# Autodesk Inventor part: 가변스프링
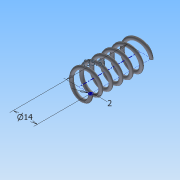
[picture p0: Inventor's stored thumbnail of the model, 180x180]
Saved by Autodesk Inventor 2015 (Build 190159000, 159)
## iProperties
Created: 2020-02
Part Number: 가변스프링
Material: 일반
Document SubType Name: Modeling
Designer: user
Density: 1 g/cm^3
Appearance: 기본값
Mass: 0.819106 g
Surface Area: 16.6202 cm^2
Volume: 0.819106 cm^3
Author: user
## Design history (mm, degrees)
sketch "스케치1"
  geometry: L1 (0, 0)-(7, 0); L2 (7, 0)-(7, 35.5); L3 (7, 35.5)-(0, 35.5); L4 (0, 35.5)-(0, 0); C1 r 1 at (7, 0)
  constraints: 8 end point, 2 parallel, 1 centre point, 1 coincident, 1 horizontal, 1 perpendicular
  dimensions: "d0" = 35.5 distance of L3.end L1.start (derived); "d1" = 2 diameter of C1; "d2" = 14 diameter of L2 L4
feature "코일1" sketch "스케치1" pitch "d3" = 10; turns "d5" = 6; dims "d4" = 35.5 (= d0), "d6" = 0, angle "d7" = 90 deg, angle "d8" = 90 deg, "d9" = 0, "d10" = 0
sketch "스케치2"
  geometry: C1 r 16.111 at (0, 0); 1 further point
  constraints: 1 centre point, 1 coincident
extrude "돌출1" cut sketch "스케치2" distance "d11" = 10; taper "d12" = 0 deg
node "작업 평면1"
sketch "스케치3"
  geometry: C1 r 16.525 at (7, 0); 1 further point
  constraints: 1 centre point, 1 coincident
extrude "돌출2" cut sketch "스케치3" distance "d14" = 10; taper "d15" = 0 deg
node "솔리드1"
other parameters: "d13" = 90 deg
